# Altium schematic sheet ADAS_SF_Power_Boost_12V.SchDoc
size 431 x 279 mm; Date: Not shown in title block; ApprovedBy: Not shown in title block; CheckedBy: Not shown in title block; Author: Not shown in title block; CompanyName: Not shown in title block; Engineer: Not shown in title block; Organization: Not shown in title block; Address1: Not shown in title block; Address2: Not shown in title block; Address3: Not shown in title block; Address4: Not shown in title block; DocumentNumber: 1; Revision: Use project parameter SCH_Rev; SheetNumber: 4; SheetTotal: 15; PageSetup: Record=PageOptions¦CenterHorizontal=True¦CenterVertical=True¦PrintScale=1.00¦XCorrection=1.00¦YCorrection=1.00¦PrintKind=0¦BorderSize=5000000¦LeftOffset=0¦BottomOffset=0¦Orientation=2¦PaperLength=1000¦PaperWidth=1000¦Scale=100¦PaperSource=15¦PrintQuality=600¦MediaType=1¦DitherType=10¦PaperKind=Letter¦PrintScaleMode=1
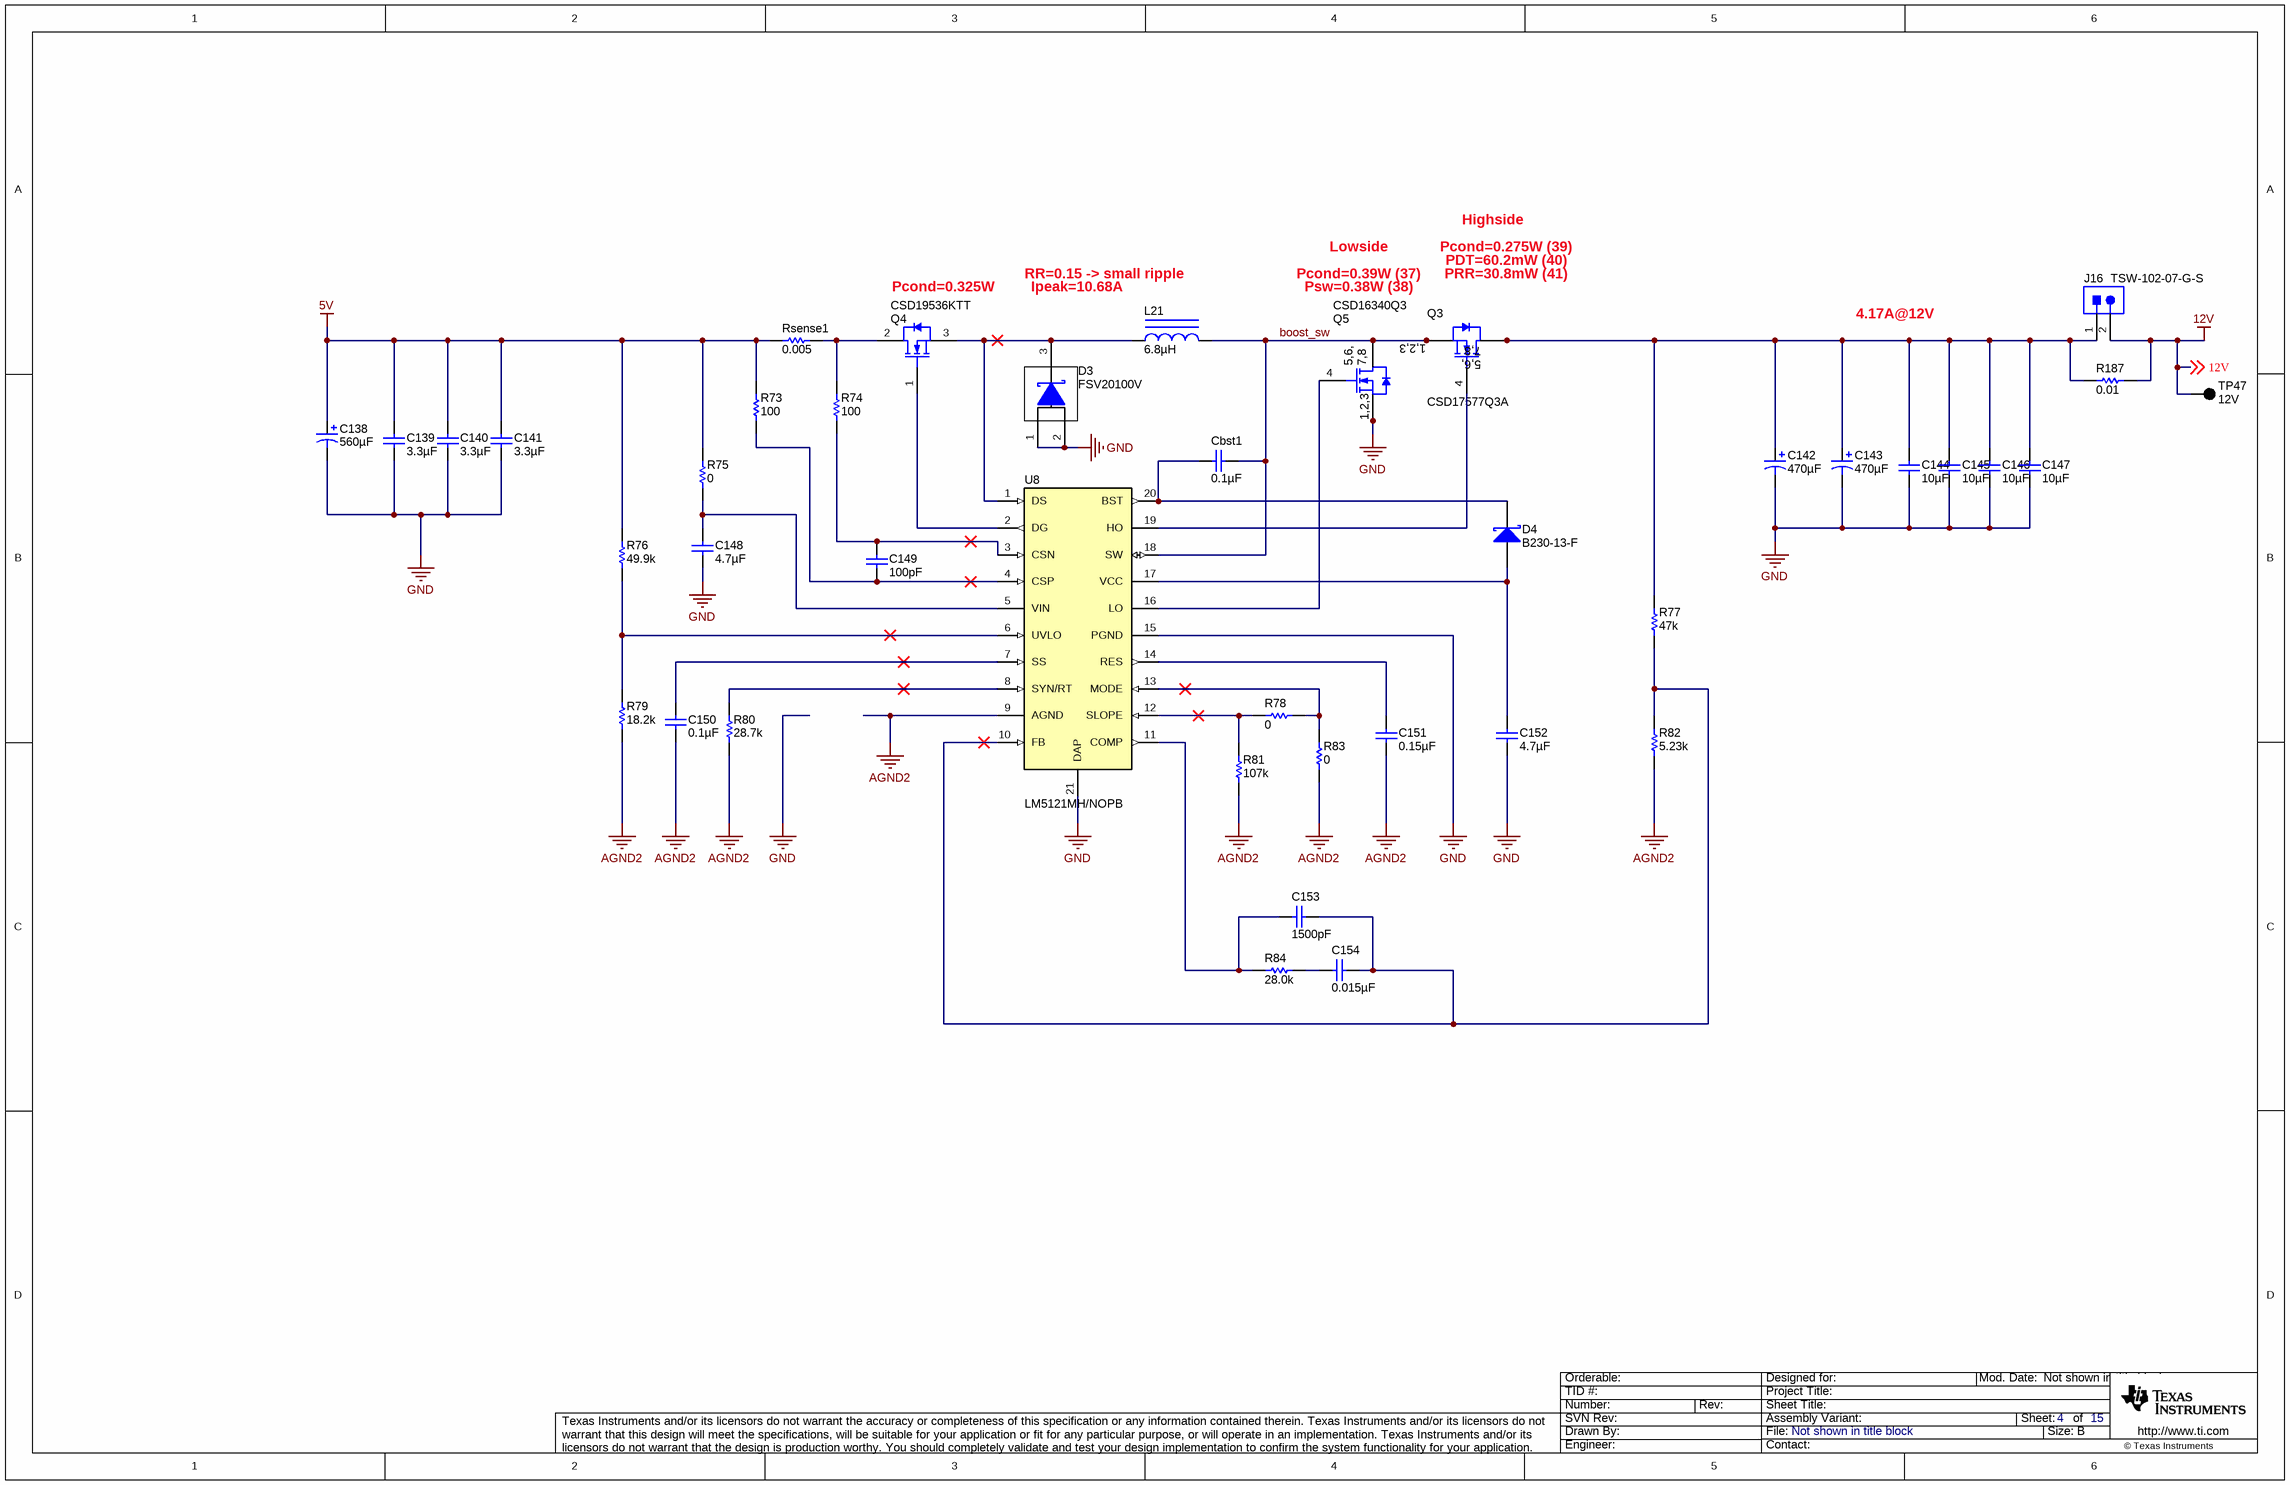
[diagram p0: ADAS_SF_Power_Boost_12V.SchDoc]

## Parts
C138  ValueDisplayed: 560µF  [Panasonic_G]  (hidden comment: EEEFPE561UAP)
C139  ValueDisplayed: 3.3µF  [0805_HV]  (hidden comment: GRM21BC81E335KA73L)
C140  ValueDisplayed: 3.3µF  [0805_HV]  (hidden comment: GRM21BC81E335KA73L)
C141  ValueDisplayed: 3.3µF  [0805_HV]  (hidden comment: GRM21BC81E335KA73L)
C142  ValueDisplayed: 470µF  [CAPSMT_62_JC0]  (hidden comment: 16SVPE470M)
C143  ValueDisplayed: 470µF  [CAPSMT_62_JC0]  (hidden comment: 16SVPE470M)
C144  ValueDisplayed: 10µF  [0805_HV]  (hidden comment: CL21A106KAFN3NE)
C145  ValueDisplayed: 10µF  [0805_HV]  (hidden comment: CL21A106KAFN3NE)
C146  ValueDisplayed: 10µF  [0805_HV]  (hidden comment: CL21A106KAFN3NE)
C147  ValueDisplayed: 10µF  [0805_HV]  (hidden comment: CL21A106KAFN3NE)
C148  ValueDisplayed: 4.7µF  [0603]  (hidden comment: GRM188R61E475KE11D)
C149  ValueDisplayed: 100pF  [0402]  (hidden comment: GRM1555C1H101JA01D)
C150  ValueDisplayed: 0.1µF  [0402]  (hidden comment: GCM155R71H104KE02D)
C151  ValueDisplayed: 0.15µF  [0402]  (hidden comment: GRM155R61A154KE19D)
C152  ValueDisplayed: 4.7µF  [0805_HV]  (hidden comment: GRM21BC71H475KE11K)
C153  ValueDisplayed: 1500pF  [0402]  (hidden comment: GRM155R71H152KA01D)
C154  ValueDisplayed: 0.015µF  [0402]  (hidden comment: CGA2B3X7R1H153K050BB)
Cbst1  ValueDisplayed: 0.1µF  [0603]  (hidden comment: GRM188R72A104KA35D)
D3  FSV20100V  [TO-277A]
D4  B230-13-F  [SMB]
J16  TSW-102-07-G-S  [TSW-102-07-G-S]
L21  ValueDisplayed: 6.8µH  [XAL1010]  (hidden comment: XAL1010-682MEB)
Q3  CSD17577Q3A  [TRANS_NexFET_Q3A]
Q4  CSD19536KTT  [KTT0002A_N]
Q5  CSD16340Q3  [DQG0008A]
R73  ValueDisplayed: 100  [0402]  (hidden comment: CRCW0402100RFKED)
R74  ValueDisplayed: 100  [0402]  (hidden comment: CRCW0402100RFKED)
R75  ValueDisplayed: 0  [0603]  (hidden comment: CRCW06030000Z0EA)
R76  ValueDisplayed: 49.9k  [0402]  (hidden comment: CRCW040249K9FKED)
R77  ValueDisplayed: 47k  [0402]  (hidden comment: CRCW040247K0JNED)
R78  ValueDisplayed: 0  [0402]  (hidden comment: CRCW04020000Z0ED)
R79  ValueDisplayed: 18.2k  [0402]  (hidden comment: CRCW040218K2FKED)
R80  ValueDisplayed: 28.7k  [0402]  (hidden comment: CRCW040228K7FKED)
R81  ValueDisplayed: 107k  [0402]  (hidden comment: CRCW0402107KFKED)
R82  ValueDisplayed: 5.23k  [0402]  (hidden comment: CRCW04025K23FKED)
R83  ValueDisplayed: 0  [0402]  (hidden comment: CRCW04020000Z0ED)
R84  ValueDisplayed: 28.0k  [0402]  (hidden comment: CRCW040228K0FKED)
R187  ValueDisplayed: 0.01  [KRL2012]  (hidden comment: KRL2012E-M-R010-F-T5)
Rsense1  ValueDisplayed: 0.005  [0612]  (hidden comment: PRL1632-R005-F-T1)
TP47  12V  [Keystone5011]
U8  LM5121MH/NOPB  [PWP0020A_N]

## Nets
5V: C138.1(+) C139.1 C140.1 C141.1 R73.2 R75.2 R76.2 Rsense1.1
12V: J16.2 R187.2 TP47.1 ; off-sheet 12V
AGND2: C150.2 C151.2 R79.1 R80.1 R81.1 R82.1 R83.1 U8.9(AGND)
GND: C138.2(-) C139.2 C140.2 C141.2 C142.2(-) C143.2(-) C144.2 C145.2 C146.2 C147.2 C148.2 C152.2 D3.1(A) D3.2(A) Q5.1(S) Q5.2(S) Q5.3(S) U8.15(PGND) U8.21(DAP)
boost_sw: Cbst1.1 L21.2 Q3.1(S) Q3.2(S) Q3.3(S) Q5.5(D) Q5.6(D) Q5.7(D) Q5.8(D) Q5.9(D) U8.18(SW)
NetC142_1: C142.1(+) C143.1(+) C144.1 C145.1 C146.1 C147.1 J16.1 Q3.5(D) Q3.6(D) Q3.7(D) Q3.8(D) Q3.9(D) R77.2 R187.1
NetC148_1: C148.1 R75.1 U8.5(VIN)
NetC149_1: C149.1 R74.1 U8.3(CSN)
NetC149_2: C149.2 R73.1 U8.4(CSP)
NetC150_1: C150.1 U8.7(SS)
NetC151_1: C151.1 U8.14(RES)
NetC152_1: C152.1 D4.2(A) U8.17(VCC)
NetC153_1: C153.1 C154.1 R77.1 R82.2 U8.10(FB)
NetC153_2: C153.2 R84.1 U8.11(COMP)
NetC154_2: C154.2 R84.2
NetCbst1_2: Cbst1.2 D4.1(K) U8.20(BST)
NetD3_3: D3.3(K) L21.1 Q4.3(S) U8.1(DS)
NetQ3_4: Q3.4(G) U8.19(HO)
NetQ4_1: Q4.1(G) U8.2(DG)
NetQ4_2: Q4.2(D) R74.2 Rsense1.2
NetQ5_4: Q5.4(G) U8.16(LO)
NetR76_1: R76.1 R79.2 U8.6(UVLO)
NetR78_1: R78.1 R83.2 U8.13(MODE)
NetR78_2: R78.2 R81.2 U8.12(SLOPE)
NetR80_2: R80.2 U8.8(SYN/RT)

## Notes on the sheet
- Highside
- (near Q4) Pcond=0.325W
- Ipeak=10.68A
- RR=0.15 -> small ripple
- Pcond=0.39W (37)
- Psw=0.38W (38)
- Lowside
- Pcond=0.275W (39)
- PDT=60.2mW (40)
- PRR=30.8mW (41)
- 4.17A@12V

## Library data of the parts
C138 = EEEFPE561UAP: CAP, AL, 560 µF, 25 V, +/- 20%, 0.08 ohm, AEC-Q200 Grade 2, SMD; Manufacturer: Panasonic; Polarized: Y; CompType: Capacitor; Value: 560uF; U/M: EA; Cap_F: 0.00056; Tolerance_%: 20; VDC_V: 25; Value2: 25V; ESR_ohm: 0.08; IRMS_A: 0.85; TaMin_C: -55; TaMax_C: 105; Cap_Case: 10x10.2mm; AEC Category: Q200; AEC Grade: 2
C139-C141 = GRM21BC81E335KA73L: CAP, CERM, 3.3 µF, 25 V, +/- 10%, X6S, 0805; Manufacturer: MuRata; Polarized: N; CompType: Capacitor; Value: 3.3uF; U/M: EA; Cap_F: 0.0000033; Tolerance_%: 10; Value1: Unknown; VDC_V: 25; Value2: 25V; TaMin_C: -55; TaMax_C: 105; Cap_Case: 0805; SizeArea_mm2: 2.5; SizeAreaWB_mm2: 6.75; SizeX_mm: 2; SizeY_mm: 1.25; SizeZ_mm: 1.45; AEC Category: Q200
C142 C143 = 16SVPE470M: CAP, Aluminum Polymer, 470 µF, 16 V, +/- 20%, 0.01 ohm, JC0 SMD; Manufacturer: Panasonic; Polarized: Y; CompType: Capacitor; Value: 470uF; U/M: EA; Cap_F: 0.00047; Tolerance_%: 20; VDC_V: 16; Value2: 16V; ESR_ohm: 0.01; IRMS_A: 6.1; TaMin_C: -55; TaMax_C: 105; AEC Category: Q200
C144-C147 = CL21A106KAFN3NE: CAP, CERM, 10 µF, 25 V, +/- 10%, X5R, 0805; Manufacturer: Samsung Electro-Mechanics; Polarized: N; CompType: Capacitor; Value: 10uF; U/M: EA; Cap_F: 0.00001; Tolerance_%: 10; Value1: Unknown; VDC_V: 25; Value2: 25V; TaMin_C: -55; TaMax_C: 85; Cap_Case: 0805; SizeArea_mm2: 2.5; SizeAreaWB_mm2: 6.75; SizeX_mm: 2; SizeY_mm: 1.25; SizeZ_mm: 1.45; AEC Category: Q200
C148 = GRM188R61E475KE11D: CAP, CERM, 4.7 µF, 25 V, +/- 10%, X5R, 0603; Manufacturer: MuRata; Polarized: N; CompType: Capacitor; Value: 4.7uF; U/M: EA; Cap_F: 0.0000047; Tolerance_%: 10; Value1: Unknown; VDC_V: 25; Value2: 25V; TaMin_C: -55; TaMax_C: 85; SizeArea_mm2: 1.28; SizeAreaWB_mm2: 4.68; SizeX_mm: 1.6; SizeY_mm: 0.8; SizeZ_mm: 1; AEC Category: Q200
C149 = GRM1555C1H101JA01D: CAP, CERM, 100 pF, 50 V, +/- 5%, C0G/NP0, 0402; Manufacturer: MuRata; Polarized: N; CompType: Capacitor; Value: 100pF; U/M: EA; Cap_F: 0.0000000001; Tolerance_%: 5; Value1: Unknown; VDC_V: 50; Value2: 50V; TaMin_C: -55; TaMax_C: 125; SizeArea_mm2: 0.5; SizeAreaWB_mm2: 3; SizeX_mm: 1; SizeZ_mm: 0.6; AEC Category: Q200
C150 = GCM155R71H104KE02D: CAP, CERM, 0.1 µF, 50 V, +/- 10%, X7R, AEC-Q200 Grade 1, 0402; Manufacturer: MuRata; Polarized: N; CompType: Capacitor; Value: 0.1uF; U/M: EA; Cap_F: 0.0000001; Tolerance_%: 10; Value1: Unknown; VDC_V: 50; Value2: 50V; TaMin_C: -55; TaMax_C: 125; AEC Category: Q200; AEC Qualified: Y; AEC Grade: 1; SizeArea_mm2: 0.5; SizeAreaWB_mm2: 3; SizeZ_mm: 0.6
C151 = GRM155R61A154KE19D: CAP, CERM, 0.15 µF, 10 V, +/- 10%, X5R, 0402; Manufacturer: MuRata; Polarized: N; CompType: Capacitor; Value: 0.15uF; U/M: EA; Cap_F: 0.00000015; Tolerance_%: 10; Value1: Unknown; Value2: 10V; TaMin_C: -55; TaMax_C: 85; SizeArea_mm2: 0.5; SizeAreaWB_mm2: 3; SizeX_mm: 1; SizeZ_mm: 0.6; AEC Category: Q200
C152 = GRM21BC71H475KE11K: CAP, CERM, 4.7 µF, 50 V, +/- 10%, X7S, 0805; Manufacturer: MuRata; Polarized: N; CompType: Capacitor; Value: 4.7uF; U/M: EA; Cap_F: 0.0000047; Tolerance_%: 10; Value1: Unknown; VDC_V: 50; Value2: 50V; TaMin_C: -55; TaMax_C: 125; Cap_Case: 0805; AEC Category: Q200; SizeArea_mm2: 2.5; SizeAreaWB_mm2: 6.75; SizeX_mm: 2; SizeY_mm: 1.25; SizeZ_mm: 1.45
C153 = GRM155R71H152KA01D: CAP, CERM, 1500 pF, 50 V, +/- 10%, X7R, 0402; Manufacturer: MuRata; Polarized: N; CompType: Capacitor; Value: 1500pF; U/M: EA; Cap_F: 0.0000000015; Tolerance_%: 10; Value1: Unknown; VDC_V: 50; Value2: 50V; TaMin_C: -55; TaMax_C: 125; SizeArea_mm2: 0.5; SizeAreaWB_mm2: 3; SizeX_mm: 1; SizeZ_mm: 0.6; AEC Category: Q200
C154 = CGA2B3X7R1H153K050BB: CAP, CERM, 0.015 µF, 50 V, +/- 10%, X7R, AEC-Q200 Grade 1, 0402; Manufacturer: TDK; Polarized: N; CompType: Capacitor; Value: 0.015uF; U/M: EA; Cap_F: 0.000000015; Tolerance_%: 10; ESR_ohm: 0.2162; Value1: 0.2162 ohm; VDC_V: 50; Value2: 50V; IRMS_A: 0.379389; TaMin_C: -55; TaMax_C: 125; SizeArea_mm2: 0.5; SizeAreaWB_mm2: 3; SizeX_mm: 1; SizeZ_mm: 0.6; AEC Category: Q200; AEC Qualified: Y
Cbst1 = GRM188R72A104KA35D: CAP, CERM, 0.1 µF, 100 V, +/- 10%, X7R, 0603; Manufacturer: MuRata; Polarized: N; CompType: Capacitor; Value: 0.1uF; U/M: EA; Cap_F: 0.0000001; Tolerance_%: 10; Value1: Unknown; VDC_V: 100; Value2: 100V; TaMin_C: -55; TaMax_C: 125; AEC Category: Q200; SizeArea_mm2: 1.28; SizeAreaWB_mm2: 4.68; SizeX_mm: 1.6; SizeY_mm: 0.8; SizeZ_mm: 1
D3 = FSV20100V: Diode, Schottky, 100 V, 20 A, AEC-Q101, TO-277A; Manufacturer: Fairchild Semiconductor; U/M: EA; Vf_V: 0.66; Value: 100V; Value1: 20A; Value2: 0.66V; Io_A: 20; Vr_V: 100; TJmax_C: 150; SizeAreaWB_mm2: 56.1; SizeArea_mm2: 29.9; SizeX_mm: 4.6; SizeY_mm: 6.5; SizeZ_mm: 1.2; AEC Category: Q101; AEC Qualified: Y
D4 = B230-13-F: Diode, Schottky, 30 V, 2 A, SMB; Manufacturer: Diodes Inc.; U/M: EA; Vf_V: 0.5; Value: 30V; Value1: 2A; Value2: 0.5V; Io_A: 2; Vr_V: 30; TJmax_C: 150; RJC_CperW: 20; SizeAreaWB_mm2: 44.156; SizeArea_mm2: 21.336; SizeX_mm: 5.6; SizeY_mm: 3.81; SizeZ_mm: 2.6; AEC Category: Q101
J16 = TSW-102-07-G-S: Header, 100mil, 2x1, Gold, TH; Manufacturer: Samtec; SymbolCreator: a0412235; Pitch_mm: 2.54; Gender: Male; Shrouded: N; Row_Count: 1; Current_A: 6.3; Voltage_V: 550; Cert_CSA: Y
L21 = XAL1010-682MEB: Inductor, Shielded, Composite, 6.8 µH, 18.5 A, 0.01 ohm, SMD; Manufacturer: Coilcraft; Value: 6.8uH; Ind_H: 6.8E-6; Imax_A: 18.5; Irms: 18.5A @ 40C rise; Isat: 21.8A @ 30% inductance drop; DCR_ohm: 0.01; Value2: 18.5A; AEC Category: Q200
Q3 = CSD17577Q3A: MOSFET, N-CH, 30 V, 19 A, SON 3.3x3.3mm; Manufacturer: Texas Instruments; Alternate Manufacturer: None; U/M: EA; ChType: N; Value: 30V; VdsMax_V: 30; Value1: 0.0064 ohm; Rdson45_ohm: 0.0064; Value2: 13 nC; QgTyp_nC: 13; Vgs_V: 20; IdsMax_A: 19; AEC Category: Q101
Q4 = CSD19536KTT: MOSFET, N-CH, 100 V, 200 A, TO-263-2; Manufacturer: Texas Instruments; Alternate Manufacturer: None; U/M: EA; ChType: N; Value: 100V; VdsMax_V: 100; Value1: ? ohm; Value2: 118 nC; QgTyp_nC: 118; Vgs_V: 20; IdsMax_A: 200; SizeAreaWB_mm2: 198.208; SizeArea_mm2: 145.288; SizeX_mm: 14.3; SizeY_mm: 10.16; SizeZ_mm: 4.7; AEC Category: Q101
Q5 = CSD16340Q3: MOSFET, N-CH, 25 V, 60 A, DQG0008A; Manufacturer: Texas Instruments; Alternate Manufacturer: None; U/M: EA; ChType: N; Value: 25V; VdsMax_V: 25; Value1: 0.0043 ohm; Rdson45_ohm: 0.0043; Value2: 6.5 nC; QgTyp_nC: 6.5; Vgs_V: 10; IdsMax_A: 60; AEC Category: Q101
R73 R74 = CRCW0402100RFKED: RES, 100, 1%, 0.063 W, 0402; Manufacturer: Vishay-Dale; CompType: Resistor; Value: 100; Value_Code: 100R; Tolerance_%: 1; Power_W: 0.063; Value2: 0.063W; VDC_V: 50; TempCo: 100 ppm/C; SizeArea_mm2: 0.5; SizeZ_mm: 0.6; EIA_Code: E96; U/M: EA; AEC Category: Q200
R75 = CRCW06030000Z0EA: RES, 0, 5%, 0.1 W, 0603; Manufacturer: Vishay-Dale; CompType: Resistor; Value: 0; Value_Code: 0000; Tolerance_%: 5; Power_W: 0.1; Value2: 0.1W; VDC_V: 75; TempCo: 200 ppm/C; SizeArea_mm2: 1.28; SizeX_mm: 1.6; SizeY_mm: 0.8; SizeZ_mm: 1; EIA_Code: E24; U/M: EA; AEC Category: Q200
R76 = CRCW040249K9FKED: RES, 49.9 k, 1%, 0.063 W, 0402; Manufacturer: Vishay-Dale; CompType: Resistor; Value: 49.9k; Res_ohm: 49900; Value_Code: 49k9; Tolerance_%: 1; Power_W: 0.063; Value2: 0.063W; VDC_V: 50; TempCo: 100 ppm/C; EIA_Code: E96; U/M: EA; AEC Category: Q200
R77 = CRCW040247K0JNED: RES, 47 k, 5%, 0.063 W, 0402; Manufacturer: Vishay-Dale; CompType: Resistor; Value: 47k; Res_ohm: 47000; Value_Code: 47k0; Tolerance_%: 5; Power_W: 0.063; Value2: 0.063W; VDC_V: 50; TempCo: 200 ppm/C; SizeArea_mm2: 0.5; SizeX_mm: 1; SizeZ_mm: 0.6; EIA_Code: E24; U/M: EA; AEC Category: Q200
R78 R83 = CRCW04020000Z0ED: RES, 0, 5%, 0.063 W, 0402; Manufacturer: Vishay-Dale; CompType: Resistor; Value: 0; Value_Code: 0000; Tolerance_%: 5; Power_W: 0.063; Value2: 0.063W; VDC_V: 50; TempCo: 200 ppm/C; SizeArea_mm2: 0.5; SizeX_mm: 1; SizeZ_mm: 0.6; EIA_Code: E24; U/M: EA; AEC Category: Q200
R79 = CRCW040218K2FKED: RES, 18.2 k, 1%, 0.063 W, 0402; Manufacturer: Vishay-Dale; CompType: Resistor; Value: 18.2k; Res_ohm: 18200; Value_Code: 18k2; Tolerance_%: 1; Power_W: 0.063; Value2: 0.063W; VDC_V: 50; TempCo: 100 ppm/C; SizeArea_mm2: 0.5; SizeZ_mm: 0.6; EIA_Code: E96; U/M: EA; AEC Category: Q200
R80 = CRCW040228K7FKED: RES, 28.7 k, 1%, 0.063 W, 0402; Manufacturer: Vishay-Dale; CompType: Resistor; Value: 28.7k; Res_ohm: 28700; Value_Code: 28k7; Tolerance_%: 1; Power_W: 0.063; Value2: 0.063W; VDC_V: 50; TempCo: 100 ppm/C; EIA_Code: E96; U/M: EA; AEC Category: Q200
R81 = CRCW0402107KFKED: RES, 107 k, 1%, 0.063 W, 0402; Manufacturer: Vishay-Dale; CompType: Resistor; Value: 107k; Res_ohm: 107000; Tolerance_%: 1; Power_W: 0.063; Value2: 0.063W; VDC_V: 50; TempCo: 100 ppm/C; SizeArea_mm2: 0.5; SizeZ_mm: 0.6; EIA_Code: E96; U/M: EA; AEC Category: Q200
R82 = CRCW04025K23FKED: RES, 5.23 k, 1%, 0.063 W, 0402; Manufacturer: Vishay-Dale; CompType: Resistor; Value: 5.23k; Res_ohm: 5230; Value_Code: 5k23; Tolerance_%: 1; Power_W: 0.063; Value2: 0.063W; VDC_V: 50; TempCo: 100 ppm/C; EIA_Code: E96; U/M: EA; AEC Category: Q200
R84 = CRCW040228K0FKED: RES, 28.0 k, 1%, 0.063 W, 0402; Manufacturer: Vishay-Dale; CompType: Resistor; Value: 28.0k; Res_ohm: 28000; Value_Code: 28k0; Tolerance_%: 1; Power_W: 0.063; Value2: 0.063W; VDC_V: 50; TempCo: 100 ppm/C; EIA_Code: E96; U/M: EA; AEC Category: Q200
R187 = KRL2012E-M-R010-F-T5: RES, 0.01, 1%, 1 W, AEC-Q200 Grade 0, 0508; Manufacturer: Susumu Co Ltd; CompType: Resistor; Value: 0.01; Value_Code: R010; Tolerance_%: 1; Value2: 1W; TempCo: 25 ppm/C; EIA_Code: E96; U/M: EA; AEC Category: Q200; AEC Qualified: Y; AEC Grade: 0
Rsense1 = PRL1632-R005-F-T1: RES, 0.005, 1%, 1 W, 0612; Manufacturer: Susumu Co Ltd; CompType: Resistor; Value: 0.005; Value_Code: 5L000; Tolerance_%: 1; Value2: 1W; TempCo: 350 ppm/C; EIA_Code: E96; U/M: EA; AEC Category: Q200
TP47 = 5011: Test Point, Multipurpose, Black, TH; Manufacturer: Keystone; CompType: Test Point Loop; U/M: EA
U8 = CMP-0066109-3: 3-65V Wide Vin, Current Mode Synchronous Boost with Disconnection Switch Control, PWP0020A (HTSSOP-20); Alternate Manufacturer: Texas Instruments; Green_Lifecycle: Active; SizeAreaWB_mm2: 71.4; Green_REACh: Passed; SizeZ_mm: 1.2; SizeX_mm: 6.4; SizeY_mm: 6.5; SizeArea_mm2: 41.6; CompType: IC; AEC Category: Q200; AEC Qualified: N; Rating: Catalog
